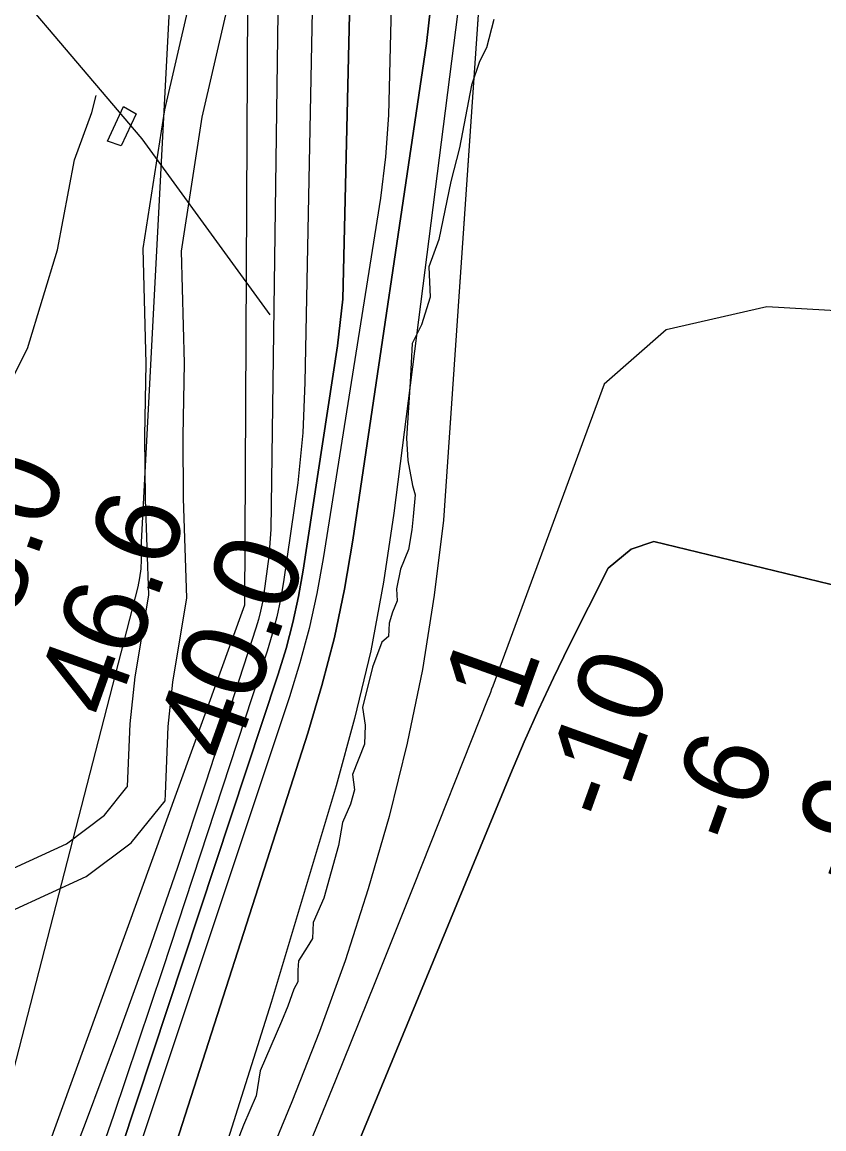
# Model space of a CAD drawing. Extents: x 3180038 to 3217926, y 922069 to 947485.
# Drawn here: x 3192206 to 3192838, y 943881 to 944753 of the extents above; entities that cross this region are included whole.
import ezdxf

# ---------------------------------------------------------------- set-up
doc = ezdxf.new("R2010")
doc.units = 0
for name, color, linetype in [('V-BRDG-OTLN', 7, 'Continuous'), ('V-RIVR-EDGE', 7, 'Continuous'), ('V-RIVR-RANG', 7, 'Continuous'), ('V-ROAD-CNTR', 7, 'Continuous'), ('V-TOPO-DPTH', 7, 'Continuous'), ('V-TOPO-MAJR', 7, 'Continuous'), ('V-TOPO-MINR', 7, 'Continuous'), ('V-TOPO-SHOR', 7, 'Continuous'), ('V-TOPO-WATR', 7, 'Continuous')]:
    doc.layers.add(name, color=color, linetype=linetype)

msp = doc.modelspace()

# ---------------------------------------------------------------- linework, layer by layer
at = {"layer": 'V-BRDG-OTLN'}
msp.add_lwpolyline([(3192296.16, 944680.41), (3192284.26, 944655.29), (3192273.61, 944659.01), (3192286.14, 944686.19)], close=True, dxfattribs=at)
at = {"layer": 'V-RIVR-EDGE'}
msp.add_lwpolyline([(3192577.81, 944754.68), (3192572.05, 944732.4), (3192566.32, 944721.52), (3192560.05, 944702.87), (3192550.59, 944653.62), (3192543.78, 944627.19), (3192534.34, 944581.57), (3192526.5, 944559.81), (3192527.48, 944535.95), (3192520.69, 944514.18), (3192513.39, 944499.68), (3192511.76, 944469.09), (3192509.06, 944425.01), (3192510.05, 944407.37), (3192513.63, 944387.66), (3192515.69, 944380.39), (3192514.09, 944363.28), (3192513.03, 944352.91), (3192510.39, 944337.36), (3192504.13, 944321.82), (3192500.98, 944306.27), (3192501.48, 944296.93), (3192497.83, 944288.12), (3192495.21, 944279.31), (3192494.67, 944268.94), (3192489.47, 944264.29), (3192482.16, 944244.6), (3192474.3, 944212.98), (3192476.34, 944198.97), (3192475.79, 944183.93), (3192466.39, 944160.1), (3192467.92, 944148.17), (3192464.78, 944136.77), (3192458.52, 944122.26), (3192455.36, 944104.12), (3192443.85, 944062.65), (3192435.5, 944043.49), (3192434.96, 944031.04), (3192430.79, 944024.31), (3192424.02, 944013.43), (3192423.48, 944006.17), (3192423.46, 943996.84), (3192420.33, 943991.14), (3192415.63, 943977.67), (3192410.42, 943965.75), (3192393.73, 943926.9), (3192390.57, 943907.2), (3192380.65, 943883.89), (3192358.73, 943827.93)], dxfattribs=at)
at = {"layer": 'V-ROAD-CNTR'}
for points in [[(3192288.88, 944150.06), (3192289.4, 944150.71), (3192291.45, 944200.12), (3192295.36, 944236.98), (3192305.97, 944301.34), (3192303.46, 944376.92), (3192303.04, 944426.69), (3192304.03, 944483.83), (3192301.73, 944574.25), (3192318.56, 944683.52), (3192346.98, 944806.49), (3192368.43, 944930.53), (3192400.33, 945022), (3192400.84, 945025.15)], [(3192319.18, 944144.62), (3192321.39, 944197.91), (3192325.1, 944232.96), (3192336.05, 944299.38), (3192333.45, 944377.55), (3192333.04, 944426.56), (3192334.04, 944483.96), (3192331.79, 944572.33), (3192348.04, 944677.85), (3192376.4, 944800.55), (3192397.57, 944922.99), (3192429.52, 945014.59), (3192429.74, 945015.93)], [(3192088.03, 944026.98), (3192111.46, 944029.62), (3192152.36, 944058.14), (3192182.68, 944078.72), (3192241.26, 944105.68), (3192271.07, 944128.15), (3192288.88, 944150.06)], [(3192091.38, 943997.17), (3192122.38, 944000.66), (3192169.36, 944033.43), (3192197.48, 944052.51), (3192256.74, 944079.78), (3192292.04, 944106.4), (3192318.97, 944139.51), (3192319.18, 944144.62)]]:
    msp.add_lwpolyline(points, dxfattribs=at)
at = {"layer": 'V-TOPO-DPTH'}
for points in [[(3192577.1, 945689.3), (3192629.22, 945689.18), (3192538.13, 944360.37), (3192530.83, 944301.44), (3192521.58, 944242.86), (3192509.42, 944184.82), (3192495.33, 944127.13), (3192478.69, 944070.08), (3192460.61, 944013.52), (3192440.38, 943957.7), (3192418.72, 943902.36), (3192179.74, 943324.81), (3192169.57, 943300.58), (3192159.23, 943276.41), (3192148.64, 943252.36), (3192137.88, 943228.37), (3192075.61, 943091.38), (3192033.27, 942999.1), (3191990.51, 942907.02), (3191947.11, 942815.24), (3191903.29, 942723.66), (3191733.21, 942371.38), (3191695.21, 942389.79)], [(3191695.21, 942389.79), (3191725.96, 942453.66), (3191741.3, 942485.62), (3191756.57, 942517.6), (3191771.77, 942549.63), (3191786.9, 942581.68), (3192117.54, 943284.24), (3192119.87, 943289.26), (3192122.16, 943294.29), (3192124.4, 943299.35), (3192126.61, 943304.43), (3192163.14, 943389.63), (3192182.9, 943437.57), (3192201.74, 943485.86), (3192219.21, 943534.66), (3192235.76, 943583.8), (3192431.31, 944192.69), (3192442.34, 944230.19), (3192452.13, 944267.98), (3192460.06, 944306.21), (3192466.74, 944344.73), (3192524.72, 944735.76), (3192527.89, 944763.61), (3192577.1, 945689.3)], [(3192577.1, 945689.3), (3192527.89, 944763.61), (3192524.72, 944735.76), (3192466.74, 944344.73), (3192460.06, 944306.21), (3192452.13, 944267.98), (3192442.34, 944230.19), (3192431.31, 944192.69), (3192235.76, 943583.8), (3192219.21, 943534.66), (3192201.74, 943485.86), (3192182.9, 943437.57), (3192163.14, 943389.63), (3192126.61, 943304.43), (3192124.4, 943299.35), (3192122.16, 943294.29), (3192119.87, 943289.26), (3192117.54, 943284.24), (3191786.9, 942581.68), (3191771.77, 942549.63), (3191756.57, 942517.6), (3191741.3, 942485.62), (3191725.96, 942453.66), (3191695.21, 942389.79)], [(3191661.05, 942406.32), (3191945.96, 943002.33), (3191970.14, 943053.51), (3191994, 943104.84), (3192017.38, 943156.39), (3192040.44, 943208.08), (3192057.49, 943246.78), (3192071.59, 943279.32), (3192085.42, 943311.96), (3192098.86, 943344.77), (3192112.02, 943377.7), (3192133.69, 943432.85), (3192156.99, 943493.62), (3192179.61, 943554.63), (3192201.23, 943616), (3192222.18, 943677.61), (3192407.99, 944239.23), (3192414.1, 944259.41), (3192419.53, 944279.75), (3192423.94, 944300.33), (3192427.65, 944321.09), (3192454.72, 944497.74), (3192458.84, 944534.55), (3192480.1, 945442.54)], [(3192668.27, 945195.28), (3192595.89, 945202.95), (3192538.13, 944360.37), (3192530.83, 944301.44), (3192521.58, 944242.86), (3192509.42, 944184.82), (3192495.33, 944127.13), (3192478.69, 944070.08), (3192460.61, 944013.52), (3192440.38, 943957.7), (3192418.72, 943902.36), (3192179.74, 943324.81), (3192169.57, 943300.58), (3192159.23, 943276.41), (3192148.64, 943252.36), (3192137.88, 943228.37), (3192075.61, 943091.38), (3192033.27, 942999.1), (3191990.51, 942907.02), (3191947.11, 942815.24), (3191903.29, 942723.66), (3191733.21, 942371.38)], [(3192335.47, 943541.64), (3192590.8, 944160.38), (3192601.64, 944185.87), (3192612.86, 944211.19), (3192624.62, 944236.25), (3192636.76, 944261.15), (3192667.6, 944322.7), (3192685.87, 944337.69), (3192703.62, 944343.55), (3192885.6, 944299.42)], [(3192335.47, 943541.64), (3192590.8, 944160.38), (3192601.64, 944185.87), (3192612.86, 944211.19), (3192624.62, 944236.25), (3192636.76, 944261.15), (3192667.6, 944322.7), (3192685.87, 944337.69), (3192703.62, 944343.55), (3192885.6, 944299.42)]]:
    msp.add_lwpolyline(points, dxfattribs=at)
at = {"layer": 'V-TOPO-MAJR'}
msp.add_lwpolyline([(3192382.03, 945583.34), (3192385.74, 945570.19), (3192388.62, 945549.21), (3192389.57, 945527.83), (3192389.51, 945525.47), (3192387.48, 945505.38), (3192381.45, 944293.47), (3192038.75, 943349.22), (3192036.4, 943342.99), (3192033.95, 943336.8), (3192031.34, 943330.67), (3192028.63, 943324.59), (3191756.01, 942733.06), (3191732.5, 942682.34), (3191708.82, 942631.68), (3191684.92, 942581.13), (3191660.86, 942530.66), (3191612.52, 942429.82)], dxfattribs=at)
at = {"layer": 'V-TOPO-MINR'}
for points in [[(3192629.22, 945689.18), (3192538.13, 944360.37), (3192530.83, 944301.44), (3192521.58, 944242.86), (3192509.42, 944184.82), (3192495.33, 944127.13), (3192478.69, 944070.08), (3192460.61, 944013.52), (3192440.38, 943957.7), (3192418.72, 943902.36), (3192179.74, 943324.81), (3192169.57, 943300.58), (3192159.23, 943276.41), (3192148.64, 943252.36), (3192137.88, 943228.37), (3192075.61, 943091.38), (3192033.27, 942999.1), (3191990.51, 942907.02), (3191947.11, 942815.24), (3191903.29, 942723.66), (3191733.21, 942371.38)], [(3192418.08, 945535.13), (3192402.2, 944353.19), (3192400.45, 944331.74), (3192396.58, 944302.72), (3192395.46, 944295.78), (3192394.1, 944288.9), (3192392.36, 944282.1), (3192390.37, 944275.36), (3192351.01, 944154.16), (3192328.65, 944087.04), (3192305.6, 944020.16), (3192281.52, 943953.65), (3192256.76, 943887.37), (3192053.08, 943354.75), (3192048.61, 943343.32), (3192044.03, 943331.94), (3192039.27, 943320.63), (3192034.39, 943309.36), (3191887.66, 942977.19), (3191845.97, 942883.98), (3191803.71, 942791.03), (3191760.6, 942698.47), (3191716.92, 942606.18), (3191628.7, 942421.99)], [(3192361.39, 945510.99), (3192299.76, 944338.21), (3192299.88, 944336.63), (3192300.08, 944329.36), (3192299.81, 944322.14), (3192298.82, 944314.98), (3192297.36, 944307.86), (3192134.55, 943676.1), (3192119.12, 943619.36), (3192102.69, 943562.93), (3192084.75, 943506.96), (3192065.82, 943451.3), (3192028.02, 943344.87), (3192026.33, 943340.48), (3192025.39, 943338.33), (3192024.42, 943336.19), (3191620.6, 942488.33), (3191616.57, 942479.88), (3191612.54, 942471.43), (3191608.5, 942462.98), (3191604.45, 942454.53), (3191596.35, 942437.65)], [(3192448.94, 945479.94), (3192428.89, 944468.85), (3192427.29, 944429.31), (3192423.34, 944389.76), (3192412.03, 944311.91), (3192409.65, 944298.06), (3192406.8, 944284.32), (3192403.24, 944270.75), (3192399.21, 944257.29), (3192317.16, 944007.07), (3192278.32, 943891.73), (3192238.26, 943776.82)], [(3192480.1, 945442.54), (3192458.84, 944534.55), (3192454.72, 944497.74), (3192427.65, 944321.09), (3192423.94, 944300.33), (3192419.53, 944279.75), (3192414.1, 944259.41), (3192407.99, 944239.23), (3192222.18, 943677.61), (3192201.23, 943616), (3192179.61, 943554.63), (3192156.99, 943493.62), (3192133.69, 943432.85), (3192112.02, 943377.7), (3192098.86, 943344.77), (3192085.42, 943311.96), (3192071.59, 943279.32), (3192057.49, 943246.78), (3192040.44, 943208.08), (3192017.38, 943156.39), (3191994, 943104.84), (3191970.14, 943053.51), (3191945.96, 943002.33), (3191661.05, 942406.32)], [(3192512.9, 945420.77), (3192494.7, 944679.48), (3192492.41, 944646.66), (3192488.46, 944613.89), (3192443.36, 944330.24), (3192438.26, 944302.6), (3192432.27, 944275.17), (3192424.93, 944248.07), (3192416.7, 944221.2), (3192133.84, 943373.09), (3192129.71, 943361.05), (3192125.44, 943349.06), (3192120.98, 943337.15), (3192116.38, 943325.28), (3192115.41, 943322.84), (3192111.13, 943312.25), (3192106.78, 943301.7), (3192102.32, 943291.19), (3192097.78, 943280.72), (3192093.13, 943270.29), (3192088.42, 943259.89), (3192083.62, 943249.54), (3192078.74, 943239.21), (3191677.23, 942398.49)], [(3192562.29, 944861.94), (3192499.09, 944365.83), (3192490.81, 944311.51), (3192480.76, 944257.56), (3192468.06, 944204.18), (3192453.6, 944151.17), (3192402.48, 943980.5), (3192365.05, 943862.46), (3192325.12, 943745.3), (3192281.45, 943629.49), (3192235.28, 943514.57), (3192150.79, 943313.63), (3192144.92, 943299.89), (3192138.96, 943286.19), (3192132.86, 943272.55), (3192126.67, 943258.95), (3191950.4, 942877.41), (3191911.74, 942794.27), (3191872.8, 942711.26), (3191833.46, 942628.45), (3191793.85, 942545.76), (3191714.21, 942380.58)], [(3192915.11, 944521.25), (3192792.57, 944528.34), (3192713.41, 944510.2), (3192664.64, 944467.65), (3192576.91, 944229.83), (3192575.97, 944227.27), (3192575.01, 944224.72), (3192574.04, 944222.18), (3192573.04, 944219.64), (3192514.45, 944072.31), (3192483.99, 943996.17), (3192453.33, 943920.11), (3192422.38, 943844.17)], [(3192885.6, 944299.42), (3192703.62, 944343.55), (3192685.87, 944337.69), (3192667.6, 944322.7), (3192636.76, 944261.15), (3192624.62, 944236.25), (3192612.86, 944211.19), (3192601.64, 944185.87), (3192590.8, 944160.38), (3192335.47, 943541.64)]]:
    msp.add_lwpolyline(points, dxfattribs=at)
at = {"layer": 'V-TOPO-SHOR'}
for points in [[(3192401.55, 944522.18), (3192300.79, 944660.78), (3192147.09, 944841.5), (3192084.6, 944909.06), (3191684.31, 945373.53), (3191555.95, 945508.64), (3191385.36, 945338.06), (3191358.34, 945204.63), (3191381.99, 945152.27)], [(3192196.92, 944468.66), (3192210.43, 944495.68), (3192234.07, 944573.37), (3192247.59, 944644.31), (3192261.1, 944681.47), (3192264.48, 944694.98)]]:
    msp.add_lwpolyline(points, dxfattribs=at)
at = {"layer": 'V-TOPO-WATR'}
msp.add_lwpolyline([(3192577.1, 945689.3), (3192527.89, 944763.61), (3192524.72, 944735.76), (3192466.74, 944344.73), (3192460.06, 944306.21), (3192452.13, 944267.98), (3192442.34, 944230.19), (3192431.31, 944192.69), (3192235.76, 943583.8), (3192219.21, 943534.66), (3192201.74, 943485.86), (3192182.9, 943437.57), (3192163.14, 943389.63), (3192126.61, 943304.43), (3192124.4, 943299.35), (3192122.16, 943294.29), (3192119.87, 943289.26), (3192117.54, 943284.24), (3191786.9, 942581.68), (3191771.77, 942549.63), (3191756.57, 942517.6), (3191741.3, 942485.62), (3191725.96, 942453.66), (3191695.21, 942389.79)], dxfattribs=at)

# ---------------------------------------------------------------- texts
at = {"layer": 'V-RIVR-RANG'}
for s, p in [('48.0', (3192183.55, 944234.62)), ('46.6', (3192278.14, 944202.15)), ('40.0', (3192372.01, 944167.69)), ('1', (3192598.43, 944206.8)), ('-10', (3192673.65, 944120.18)), ('-6', (3192773.3, 944101.86)), ('-9', (3192867.62, 944068.64))]:
    msp.add_text(s, height=67, rotation=70.30833, dxfattribs=at).set_placement(p)

doc.saveas('drawing.dxf')
